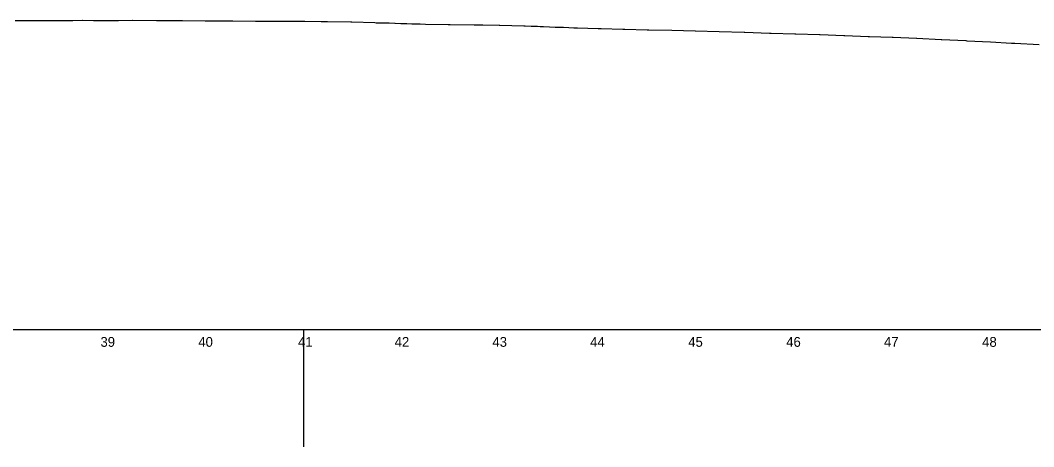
# Model space of a CAD drawing. Extents: x 579185 to 595036, y -53221 to -44640.
# Drawn here: x 582099 to 583133, y -45119 to -44684 of the extents above; entities that cross this region are included whole.
import ezdxf

# ---------------------------------------------------------------- set-up
doc = ezdxf.new("R2010")
doc.units = 0
for name, color, linetype in [('Default', 7, 'Continuous'), ('Exist Profile Cell', 7, 'Continuous'), ('Exist Vertical Profile Ground Line', 7, 'Continuous'), ('Exist Vertical Profile Horizontal Axis Label Major', 7, 'Continuous')]:
    doc.layers.add(name, color=color, linetype=linetype)

msp = doc.modelspace()

# ---------------------------------------------------------------- linework, layer by layer
at = {"layer": 'Default'}
msp.add_line((582387.9, -45119.4), (582387.9, -45000), dxfattribs=at)
at = {"layer": 'Exist Profile Cell'}
msp.add_line((579221, -45000), (594884.8, -45000), dxfattribs=at)
at = {"layer": 'Exist Vertical Profile Ground Line'}
for points in [[(582093.3, -44684.7), (582103.3, -44684.7), (582113, -44684.7), (582124.3, -44684.7), (582134.3, -44684.7), (582143.5, -44684.6), (582152.1, -44684.5), (582161.8, -44684.3), (582162.1, -44684.3), (582173.4, -44684.6), (582177.1, -44684.6), (582184.4, -44684.6), (582191, -44684.5), (582198.9, -44684.4), (582213, -44684.3), (582213.6, -44684.3), (582237.6, -44684.4), (582238.9, -44684.4), (582262.7, -44684.7), (582264.2, -44684.7), (582287.2, -44684.8), (582288.9, -44684.8), (582311.8, -44685), (582313.6, -44685), (582315.4, -44685), (582338.6, -44685.1), (582340.5, -44685.1), (582363.5, -44685.2), (582365.6, -44685.2), (582387.9, -44685.3), (582389, -44685.4), (582405.6, -44685.5)], [(582405.6, -44685.5), (582411.8, -44685.5), (582412.2, -44685.5), (582435.9, -44686), (582437.1, -44686), (582460.4, -44686.7), (582462, -44686.8), (582467.9, -44686.9), (582474.1, -44687.1), (582475, -44687.1), (582480.8, -44687.3), (582481.2, -44687.3), (582487.1, -44687.5), (582493, -44687.7), (582498.4, -44687.8), (582500.9, -44687.9), (582506.6, -44688), (582512.2, -44688.2), (582535.4, -44688.5), (582537.3, -44688.6), (582561.9, -44688.9), (582562.2, -44688.9), (582570.6, -44689.1), (582587.4, -44689.4), (582588.1, -44689.4), (582612.7, -44690), (582614, -44690.1), (582620, -44690.3), (582626.2, -44690.5), (582626.6, -44690.5), (582629.2, -44690.6), (582632.8, -44690.7), (582638.8, -44690.9), (582644.4, -44691.2), (582649.5, -44691.4), (582652.9, -44691.5), (582658.4, -44691.7), (582663.7, -44691.9), (582667.4, -44692), (582688.6, -44692.8), (582691.4, -44692.8), (582713.5, -44693.5), (582715.7, -44693.5), (582738.6, -44694), (582740, -44694), (582763.5, -44694.5), (582787.4, -44695.1), (582787.8, -44695.1), (582811.8, -44695.7), (582812.1, -44695.8), (582837.5, -44696.6), (582838.2, -44696.6), (582863.3, -44697.4), (582864.2, -44697.4), (582865.1, -44697.4), (582889.2, -44698.1), (582890.1, -44698.2), (582914.2, -44698.9), (582915.1, -44699), (582939.2, -44699.8), (582940.3, -44699.9), (582964.1, -44700.8), (582965.5, -44700.8), (582988.7, -44701.6), (582989.6, -44701.7), (583013.3, -44702.6), (583013.7, -44702.6), (583038.6, -44703.8), (583039.3, -44703.9), (583063.8, -44705.1), (583064.8, -44705.2), (583089, -44706.4), (583110.2, -44707.6), (583113.8, -44707.8), (583138.6, -44709)]]:
    msp.add_lwpolyline(points, dxfattribs=at)

# ---------------------------------------------------------------- texts
at = {"layer": 'Exist Vertical Profile Horizontal Axis Label Major'}
for s, p in [('39', (582180.4, -45017.5)), ('40', (582280.3, -45017.5)), ('41', (582382.1, -45017.5)), ('42', (582480.7, -45017.5)), ('43', (582580.5, -45017.5)), ('44', (582680.3, -45017.5)), ('45', (582780.4, -45017.5)), ('46', (582880.4, -45017.5)), ('47', (582980.2, -45017.5)), ('48', (583080.4, -45017.5))]:
    msp.add_text(s, height=10, dxfattribs=at).set_placement(p)

doc.saveas('drawing.dxf')
